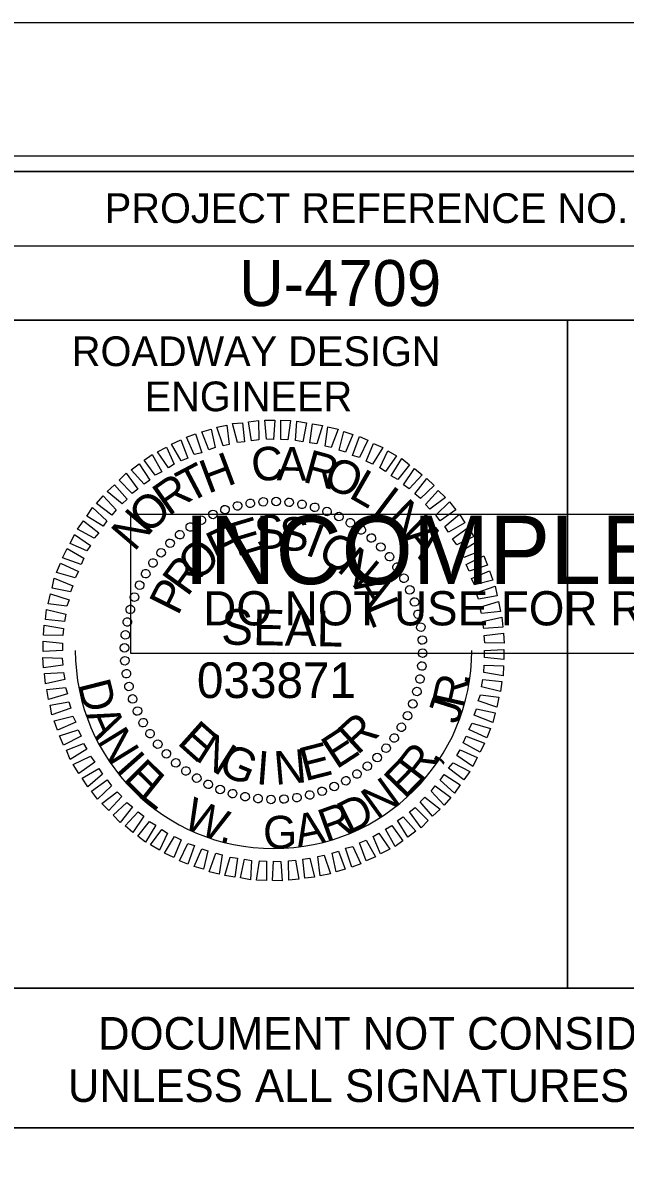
# Model space of a CAD drawing. Extents: x 1779926 to 1781610, y 620464 to 621564.
# Drawn here: x 1781401.3 to 1781502.7, y 621371.7 to 621564.2 of the extents above; entities that cross this region are included whole.
import ezdxf

# ---------------------------------------------------------------- set-up
doc = ezdxf.new("R2010")
doc.units = 0
for name, color, linetype in [('Old_Level_58', 7, 'Continuous'), ('Scratch_Level_0', 7, 'Continuous'), ('Sheet Cutting Line CELL', 7, 'Continuous'), ('Sheet Data Field CELL', 7, 'Continuous'), ('Sheet Plot Border Inside CELL', 7, 'Continuous'), ('Sheet Plot Border Outside CELL', 7, 'Continuous'), ('Sheet Professional Seal CELL', 7, 'Continuous'), ('Sheet Profile CELL', 7, 'Continuous'), ('Sheet Profile Grid Major CELL', 7, 'Continuous'), ('Sheet Profile Grid Minor CELL', 7, 'Continuous'), ('Sheet Sticker Exception Certification CELL', 7, 'Continuous'), ('Sheet Sticker Incomplete CELL', 7, 'Continuous')]:
    doc.layers.add(name, color=color, linetype=linetype)

msp = doc.modelspace()

# ---------------------------------------------------------------- linework, layer by layer
at = {"layer": 'Old_Level_58'}
msp.add_lwpolyline([(1781392.96, 621378.14), (1781592.95, 621378.14), (1781592.95, 621314.19), (1781392.96, 621314.19)], close=True, dxfattribs=at)
at = {"layer": 'Scratch_Level_0'}
msp.add_arc((1781443.52, 621458.52), 33.36, 180, 360, dxfattribs=at)
at = {"layer": 'Sheet Cutting Line CELL'}
msp.add_line((1781609.96, 621564.19), (1779925.96, 621564.19), dxfattribs=at)
at = {"layer": 'Sheet Plot Border Inside CELL'}
msp.add_lwpolyline([(1779938.96, 620486.64), (1781605.46, 620486.64), (1781605.46, 621541.74), (1779938.96, 621541.74)], close=True, dxfattribs=at)
at = {"layer": 'Sheet Plot Border Outside CELL'}
msp.add_lwpolyline([(1779925.96, 620464.19), (1781609.96, 620464.19), (1781609.96, 621564.19), (1779925.96, 621564.19)], close=True, dxfattribs=at)
at = {"layer": 'Sheet Professional Seal CELL'}
for p, q in [((1781437.42, 621482.87), (1781437.42, 621482.87)), ((1781439.62, 621483.27), (1781439.62, 621483.27)), ((1781441.77, 621483.57), (1781441.77, 621483.57)), ((1781443.97, 621483.62), (1781443.97, 621483.62)), ((1781446.17, 621483.47), (1781446.17, 621483.47)), ((1781448.32, 621483.12), (1781448.32, 621483.12)), ((1781450.42, 621482.67), (1781450.42, 621482.67)), ((1781433.32, 621481.47), (1781433.32, 621481.47)), ((1781435.32, 621482.27), (1781435.32, 621482.27)), ((1781452.52, 621481.97), (1781452.52, 621481.97)), ((1781454.52, 621481.07), (1781454.52, 621481.07)), ((1781429.47, 621479.32), (1781429.47, 621479.32)), ((1781431.37, 621480.47), (1781431.37, 621480.47)), ((1781456.47, 621480.07), (1781456.47, 621480.07)), ((1781458.27, 621478.82), (1781458.27, 621478.82)), ((1781427.72, 621478.07), (1781427.72, 621478.07)), ((1781460.02, 621477.47), (1781460.02, 621477.47)), ((1781424.57, 621475.02), (1781424.57, 621475.02)), ((1781426.07, 621476.57), (1781426.07, 621476.57)), ((1781461.57, 621475.97), (1781461.57, 621475.97)), ((1781423.22, 621473.27), (1781423.22, 621473.27)), ((1781463.07, 621474.32), (1781463.07, 621474.32)), ((1781421.97, 621471.47), (1781421.97, 621471.47)), ((1781464.32, 621472.57), (1781464.32, 621472.57)), ((1781420.97, 621469.52), (1781420.97, 621469.52)), ((1781465.47, 621470.67), (1781465.47, 621470.67)), ((1781420.07, 621467.52), (1781420.07, 621467.52)), ((1781466.47, 621468.72), (1781466.47, 621468.72)), ((1781419.37, 621465.42), (1781419.37, 621465.42)), ((1781467.27, 621466.72), (1781467.27, 621466.72)), ((1781418.92, 621463.32), (1781418.92, 621463.32)), ((1781467.87, 621464.62), (1781467.87, 621464.62)), ((1781468.27, 621462.42), (1781468.27, 621462.42)), ((1781418.57, 621461.17), (1781418.57, 621461.17)), ((1781468.57, 621460.27), (1781468.57, 621460.27)), ((1781418.42, 621458.97), (1781418.42, 621458.97)), ((1781443.52, 621458.52), (1781443.52, 621458.52)), ((1781468.62, 621458.07), (1781468.62, 621458.07)), ((1781418.47, 621456.77), (1781418.47, 621456.77)), ((1781468.47, 621455.87), (1781468.47, 621455.87)), ((1781418.77, 621454.62), (1781418.77, 621454.62)), ((1781468.12, 621453.72), (1781468.12, 621453.72)), ((1781419.17, 621452.42), (1781419.17, 621452.42)), ((1781467.67, 621451.62), (1781467.67, 621451.62)), ((1781419.77, 621450.32), (1781419.77, 621450.32)), ((1781420.57, 621448.32), (1781420.57, 621448.32)), ((1781466.97, 621449.52), (1781466.97, 621449.52)), ((1781421.57, 621446.37), (1781421.57, 621446.37)), ((1781466.07, 621447.52), (1781466.07, 621447.52)), ((1781422.72, 621444.47), (1781422.72, 621444.47)), ((1781465.07, 621445.57), (1781465.07, 621445.57)), ((1781423.97, 621442.72), (1781423.97, 621442.72)), ((1781462.47, 621442.02), (1781462.47, 621442.02)), ((1781463.82, 621443.77), (1781463.82, 621443.77)), ((1781425.47, 621441.07), (1781425.47, 621441.07)), ((1781460.97, 621440.47), (1781460.97, 621440.47)), ((1781427.02, 621439.57), (1781427.02, 621439.57)), ((1781428.77, 621438.22), (1781428.77, 621438.22)), ((1781459.32, 621438.97), (1781459.32, 621438.97)), ((1781430.57, 621436.97), (1781430.57, 621436.97)), ((1781455.67, 621436.57), (1781455.67, 621436.57)), ((1781457.57, 621437.72), (1781457.57, 621437.72)), ((1781432.52, 621435.97), (1781432.52, 621435.97)), ((1781434.52, 621435.07), (1781434.52, 621435.07)), ((1781436.62, 621434.37), (1781436.62, 621434.37)), ((1781451.72, 621434.77), (1781451.72, 621434.77)), ((1781453.72, 621435.57), (1781453.72, 621435.57)), ((1781438.72, 621433.92), (1781438.72, 621433.92)), ((1781440.87, 621433.57), (1781440.87, 621433.57)), ((1781443.07, 621433.42), (1781443.07, 621433.42)), ((1781445.27, 621433.47), (1781445.27, 621433.47)), ((1781447.42, 621433.77), (1781447.42, 621433.77)), ((1781449.62, 621434.17), (1781449.62, 621434.17))]:
    msp.add_line(p, q, dxfattribs=at)
for points in [[(1781435.02, 621492.97), (1781433.97, 621496.12), (1781435.67, 621496.47), (1781436.07, 621493.22)], [(1781437.42, 621493.52), (1781436.62, 621496.72), (1781438.27, 621496.87), (1781438.62, 621493.67)], [(1781439.82, 621493.82), (1781439.27, 621497.02), (1781440.97, 621497.22), (1781441.02, 621493.97)], [(1781442.32, 621494.07), (1781442.07, 621497.32), (1781443.72, 621497.27), (1781443.52, 621494.02)], [(1781444.72, 621494.02), (1781444.72, 621497.27), (1781446.37, 621497.22), (1781445.92, 621493.97)], [(1781447.22, 621493.87), (1781447.42, 621497.12), (1781449.07, 621496.82), (1781448.42, 621493.67)], [(1781449.62, 621493.47), (1781450.07, 621496.67), (1781451.72, 621496.42), (1781450.82, 621493.32)], [(1781452.17, 621492.92), (1781452.67, 621496.17), (1781454.37, 621495.77), (1781453.22, 621492.67)], [(1781427.97, 621490.47), (1781426.37, 621493.27), (1781427.92, 621493.97), (1781429.07, 621490.92)], [(1781430.17, 621491.52), (1781428.87, 621494.42), (1781430.37, 621495.02), (1781431.42, 621491.82)], [(1781432.62, 621492.32), (1781431.47, 621495.32), (1781433.02, 621495.77), (1781433.67, 621492.67)], [(1781454.57, 621492.27), (1781455.32, 621495.37), (1781456.87, 621494.87), (1781455.62, 621491.92)], [(1781456.82, 621491.37), (1781457.97, 621494.52), (1781459.37, 621493.92), (1781457.97, 621491.02)], [(1781425.82, 621489.27), (1781423.97, 621491.97), (1781425.52, 621492.77), (1781426.77, 621489.87)], [(1781459.07, 621490.42), (1781460.32, 621493.37), (1781461.87, 621492.67), (1781460.17, 621489.87)], [(1781461.37, 621489.27), (1781462.72, 621492.12), (1781464.22, 621491.27), (1781462.32, 621488.67)], [(1781423.62, 621488.02), (1781421.77, 621490.57), (1781423.07, 621491.52), (1781424.72, 621488.62)], [(1781463.32, 621487.92), (1781465.07, 621490.82), (1781466.37, 621489.77), (1781464.42, 621487.32)], [(1781419.72, 621484.97), (1781417.52, 621487.17), (1781418.72, 621488.37), (1781420.67, 621485.67)], [(1781421.72, 621486.52), (1781419.57, 621488.92), (1781420.92, 621489.97), (1781422.67, 621487.17)], [(1781465.37, 621486.42), (1781467.22, 621489.17), (1781468.52, 621488.07), (1781466.32, 621485.72)], [(1781418.07, 621483.22), (1781415.52, 621485.27), (1781416.77, 621486.42), (1781418.87, 621484.02)], [(1781467.27, 621484.87), (1781469.32, 621487.47), (1781470.52, 621486.27), (1781468.22, 621484.12)], [(1781416.32, 621481.32), (1781413.72, 621483.27), (1781414.82, 621484.57), (1781417.02, 621482.22)], [(1781469.07, 621483.12), (1781471.22, 621485.47), (1781472.42, 621484.27), (1781469.82, 621482.32)], [(1781414.82, 621479.42), (1781412.12, 621481.12), (1781413.07, 621482.57), (1781415.47, 621480.37)], [(1781470.82, 621481.32), (1781473.12, 621483.57), (1781474.17, 621482.22), (1781471.52, 621480.32)], [(1781472.32, 621479.37), (1781474.77, 621481.47), (1781475.72, 621480.02), (1781472.92, 621478.42)], [(1781413.32, 621477.42), (1781410.52, 621478.92), (1781411.52, 621480.32), (1781414.12, 621478.32)], [(1781473.62, 621477.32), (1781476.27, 621479.22), (1781477.22, 621477.72), (1781474.32, 621476.32)], [(1781412.12, 621475.27), (1781409.27, 621476.52), (1781410.02, 621478.07), (1781412.72, 621476.22)], [(1781474.92, 621475.12), (1781477.72, 621476.87), (1781478.37, 621475.32), (1781475.52, 621474.17)], [(1781411.12, 621472.97), (1781408.02, 621474.12), (1781408.77, 621475.67), (1781411.62, 621474.07)], [(1781410.12, 621470.77), (1781407.02, 621471.67), (1781407.67, 621473.22), (1781410.67, 621471.82)], [(1781475.92, 621472.97), (1781478.87, 621474.47), (1781479.52, 621472.87), (1781476.42, 621471.87)], [(1781476.82, 621470.62), (1781479.87, 621471.92), (1781480.42, 621470.37), (1781477.32, 621469.57)], [(1781409.37, 621468.37), (1781406.27, 621469.02), (1781406.62, 621470.67), (1781409.77, 621469.42)], [(1781477.62, 621468.22), (1781480.82, 621469.37), (1781481.12, 621467.72), (1781477.97, 621467.17)], [(1781408.72, 621465.97), (1781405.62, 621466.37), (1781405.97, 621468.07), (1781409.12, 621467.02)], [(1781408.32, 621463.42), (1781405.12, 621463.72), (1781405.32, 621465.42), (1781408.57, 621464.62)], [(1781478.22, 621465.82), (1781481.37, 621466.77), (1781481.67, 621465.07), (1781478.52, 621464.77)], [(1781478.67, 621463.42), (1781481.92, 621464.12), (1781482.07, 621462.42), (1781478.87, 621462.22)], [(1781408.07, 621461.02), (1781404.82, 621461.12), (1781404.92, 621462.77), (1781408.17, 621462.22)], [(1781478.97, 621461.02), (1781482.22, 621461.42), (1781482.32, 621459.72), (1781479.07, 621459.82)], [(1781408.02, 621458.52), (1781404.77, 621458.37), (1781404.77, 621460.07), (1781408.02, 621459.72)], [(1781479.02, 621458.52), (1781482.27, 621458.67), (1781482.27, 621456.97), (1781479.02, 621457.32)], [(1781408.07, 621456.02), (1781404.82, 621455.62), (1781404.72, 621457.32), (1781407.97, 621457.22)], [(1781478.97, 621456.02), (1781482.22, 621455.92), (1781482.12, 621454.27), (1781478.87, 621454.82)], [(1781408.37, 621453.62), (1781405.12, 621452.92), (1781404.97, 621454.62), (1781408.17, 621454.82)], [(1781478.72, 621453.62), (1781481.92, 621453.32), (1781481.72, 621451.62), (1781478.47, 621452.42)], [(1781408.82, 621451.22), (1781405.67, 621450.27), (1781405.37, 621451.97), (1781408.52, 621452.27)], [(1781409.42, 621448.82), (1781406.22, 621447.67), (1781405.92, 621449.32), (1781409.07, 621449.87)], [(1781478.32, 621451.07), (1781481.42, 621450.67), (1781481.07, 621448.97), (1781477.92, 621450.02)], [(1781477.67, 621448.67), (1781480.77, 621448.02), (1781480.42, 621446.37), (1781477.27, 621447.62)], [(1781410.22, 621446.42), (1781407.17, 621445.12), (1781406.62, 621446.67), (1781409.72, 621447.47)], [(1781476.92, 621446.27), (1781480.02, 621445.37), (1781479.37, 621443.82), (1781476.37, 621445.22)], [(1781411.12, 621444.07), (1781408.17, 621442.57), (1781407.52, 621444.17), (1781410.62, 621445.17)], [(1781475.92, 621444.07), (1781479.02, 621442.92), (1781478.27, 621441.37), (1781475.42, 621442.97)], [(1781412.12, 621441.92), (1781409.32, 621440.17), (1781408.67, 621441.72), (1781411.52, 621442.87)], [(1781413.42, 621439.72), (1781410.77, 621437.82), (1781409.82, 621439.32), (1781412.72, 621440.72)], [(1781474.92, 621441.77), (1781477.77, 621440.52), (1781477.02, 621438.97), (1781474.32, 621440.82)], [(1781414.72, 621437.67), (1781412.27, 621435.57), (1781411.32, 621437.02), (1781414.12, 621438.62)], [(1781473.72, 621439.62), (1781476.52, 621438.12), (1781475.52, 621436.72), (1781472.92, 621438.72)], [(1781416.22, 621435.72), (1781413.92, 621433.47), (1781412.87, 621434.82), (1781415.52, 621436.72)], [(1781472.22, 621437.62), (1781474.92, 621435.92), (1781473.97, 621434.47), (1781471.57, 621436.67)], [(1781417.97, 621433.92), (1781415.82, 621431.57), (1781414.62, 621432.77), (1781417.22, 621434.72)], [(1781470.72, 621435.72), (1781473.32, 621433.77), (1781472.22, 621432.47), (1781470.02, 621434.82)], [(1781419.77, 621432.17), (1781417.72, 621429.57), (1781416.52, 621430.77), (1781418.82, 621432.92)], [(1781468.97, 621433.82), (1781471.52, 621431.77), (1781470.27, 621430.62), (1781468.17, 621433.02)], [(1781421.67, 621430.62), (1781419.82, 621427.87), (1781418.52, 621428.97), (1781420.72, 621431.32)], [(1781465.32, 621430.52), (1781467.47, 621428.12), (1781466.12, 621427.07), (1781464.37, 621429.87)], [(1781467.32, 621432.07), (1781469.52, 621429.87), (1781468.32, 621428.67), (1781466.37, 621431.37)], [(1781423.72, 621429.12), (1781421.97, 621426.22), (1781420.67, 621427.27), (1781422.62, 621429.72)], [(1781463.42, 621429.02), (1781465.27, 621426.47), (1781463.97, 621425.52), (1781462.32, 621428.42)], [(1781425.67, 621427.77), (1781424.32, 621424.92), (1781422.82, 621425.77), (1781424.72, 621428.37)], [(1781427.97, 621426.62), (1781426.72, 621423.67), (1781425.17, 621424.37), (1781426.87, 621427.17)], [(1781461.22, 621427.77), (1781463.07, 621425.07), (1781461.52, 621424.27), (1781460.27, 621427.17)], [(1781430.22, 621425.67), (1781429.07, 621422.52), (1781427.67, 621423.12), (1781429.07, 621426.02)], [(1781432.47, 621424.77), (1781431.72, 621421.67), (1781430.17, 621422.17), (1781431.42, 621425.12)], [(1781454.42, 621424.72), (1781455.57, 621421.72), (1781454.02, 621421.27), (1781453.37, 621424.37)], [(1781456.87, 621425.52), (1781458.17, 621422.62), (1781456.67, 621422.02), (1781455.62, 621425.22)], [(1781459.07, 621426.57), (1781460.67, 621423.77), (1781459.12, 621423.07), (1781457.97, 621426.12)], [(1781434.87, 621424.12), (1781434.37, 621420.87), (1781432.67, 621421.27), (1781433.82, 621424.37)], [(1781437.42, 621423.57), (1781436.97, 621420.37), (1781435.32, 621420.62), (1781436.22, 621423.72)], [(1781439.82, 621423.17), (1781439.62, 621419.92), (1781437.97, 621420.22), (1781438.62, 621423.37)], [(1781442.32, 621423.02), (1781442.32, 621419.77), (1781440.67, 621419.82), (1781441.12, 621423.07)], [(1781444.72, 621422.97), (1781444.97, 621419.72), (1781443.32, 621419.77), (1781443.52, 621423.02)], [(1781447.22, 621423.22), (1781447.77, 621420.02), (1781446.07, 621419.82), (1781446.02, 621423.07)], [(1781449.62, 621423.52), (1781450.42, 621420.32), (1781448.77, 621420.17), (1781448.42, 621423.37)], [(1781452.02, 621424.07), (1781453.07, 621420.92), (1781451.37, 621420.57), (1781450.97, 621423.82)]]:
    msp.add_lwpolyline(points, close=True, dxfattribs=at)
for centre, major_axis in [((1781435.35, 621482.23), (-0.234, 0.681)), ((1781437.45, 621482.86), (-0.174, 0.699)), ((1781439.59, 621483.29), (-0.113, 0.711)), ((1781441.77, 621483.54), (-0.05, 0.718)), ((1781443.96, 621483.6), (0.013, 0.72)), ((1781446.14, 621483.46), (0.075, 0.716)), ((1781448.3, 621483.14), (0.137, 0.707)), ((1781450.43, 621482.63), (0.198, 0.692)), ((1781452.51, 621481.93), (0.258, 0.672)), ((1781431.36, 621480.46), (-0.349, 0.63)), ((1781433.32, 621481.43), (-0.293, 0.658)), ((1781454.51, 621481.06), (0.316, 0.647)), ((1781456.44, 621480.02), (0.371, 0.617)), ((1781427.73, 621478.01), (-0.453, 0.56)), ((1781429.49, 621479.31), (-0.403, 0.597)), ((1781458.26, 621478.81), (0.423, 0.582)), ((1781426.1, 621476.56), (-0.5, 0.518)), ((1781459.97, 621477.45), (0.472, 0.543)), ((1781461.56, 621475.94), (0.518, 0.5)), ((1781424.59, 621474.97), (-0.543, 0.472)), ((1781463.01, 621474.3), (0.56, 0.453)), ((1781423.23, 621473.26), (-0.582, 0.423)), ((1781464.31, 621472.54), (0.597, 0.403)), ((1781422.02, 621471.44), (-0.617, 0.371)), ((1781465.45, 621470.68), (0.63, 0.349)), ((1781420.98, 621469.51), (-0.647, 0.316)), ((1781466.43, 621468.72), (0.658, 0.293)), ((1781420.1, 621467.51), (-0.672, 0.258)), ((1781467.23, 621466.69), (0.681, 0.234)), ((1781419.41, 621465.43), (-0.692, 0.198)), ((1781467.85, 621464.59), (0.699, 0.174)), ((1781418.9, 621463.31), (-0.707, 0.137)), ((1781468.29, 621462.44), (0.711, 0.113)), ((1781418.58, 621461.14), (-0.716, 0.075)), ((1781418.44, 621458.96), (-0.72, 0.013)), ((1781468.54, 621460.27), (0.718, 0.05)), ((1781418.5, 621456.77), (-0.718, -0.05)), ((1781468.59, 621458.08), (0.72, -0.013)), ((1781468.46, 621455.9), (0.716, -0.075)), ((1781418.75, 621454.6), (-0.711, -0.113)), ((1781468.14, 621453.73), (0.707, -0.137)), ((1781419.18, 621452.45), (-0.699, -0.174)), ((1781467.63, 621451.61), (0.692, -0.198)), ((1781419.8, 621450.36), (-0.681, -0.234)), ((1781466.93, 621449.53), (0.672, -0.258)), ((1781420.61, 621448.32), (-0.658, -0.293)), ((1781466.06, 621447.53), (0.647, -0.316)), ((1781421.58, 621446.36), (-0.63, -0.349)), ((1781465.02, 621445.6), (0.617, -0.371)), ((1781422.73, 621444.5), (-0.597, -0.403)), ((1781463.81, 621443.78), (0.582, -0.423)), ((1781424.03, 621442.74), (-0.56, -0.453)), ((1781462.45, 621442.07), (0.543, -0.472)), ((1781425.48, 621441.1), (-0.518, -0.5)), ((1781427.06, 621439.59), (-0.472, -0.543)), ((1781460.94, 621440.48), (0.5, -0.518)), ((1781428.78, 621438.23), (-0.423, -0.582)), ((1781457.54, 621437.73), (0.403, -0.597)), ((1781459.3, 621439.03), (0.453, -0.56)), ((1781430.6, 621437.02), (-0.371, -0.617)), ((1781432.52, 621435.98), (-0.316, -0.647)), ((1781453.72, 621435.61), (0.293, -0.658)), ((1781455.68, 621436.58), (0.349, -0.63)), ((1781434.53, 621435.11), (-0.258, -0.672)), ((1781436.61, 621434.41), (-0.198, -0.692)), ((1781438.73, 621433.9), (-0.137, -0.707)), ((1781440.9, 621433.58), (-0.075, -0.716)), ((1781447.44, 621433.75), (0.113, -0.711)), ((1781449.59, 621434.19), (0.174, -0.699)), ((1781451.68, 621434.81), (0.234, -0.681)), ((1781443.08, 621433.44), (-0.013, -0.72)), ((1781445.27, 621433.5), (0.05, -0.718))]:
    msp.add_ellipse(centre, major_axis=major_axis, ratio=0.999708, dxfattribs=at)
at = {"layer": 'Sheet Profile CELL'}
for p, q in [((1781392.91, 621526.64), (1781592.96, 621526.64)), ((1781492.96, 621514.14), (1781492.96, 621401.69))]:
    msp.add_line(p, q, dxfattribs=at)
for points in [[(1781592.96, 621539.19), (1780092.96, 621539.19), (1780092.96, 620489.19), (1781592.96, 620489.19)], [(1781392.91, 621539.19), (1781592.96, 621539.19), (1781592.96, 621514.14), (1781392.91, 621514.14)], [(1781392.91, 621514.14), (1781492.96, 621514.14), (1781492.96, 621401.64), (1781392.91, 621401.64)], [(1781492.96, 621514.14), (1781592.96, 621514.14), (1781592.96, 621401.64), (1781492.96, 621401.64)]]:
    msp.add_lwpolyline(points, close=True, dxfattribs=at)
at = {"layer": 'Sheet Profile Grid Major CELL'}
msp.add_lwpolyline([(1781142.96, 621039.19), (1781192.96, 621039.19), (1781192.96, 621539.19), (1781242.96, 621539.19), (1781242.96, 621039.19), (1781292.96, 621039.19), (1781292.96, 621539.19), (1781342.96, 621539.19), (1781342.96, 621039.19), (1781392.96, 621039.19), (1781392.96, 621539.19), (1781419.26, 621539.19)], dxfattribs=at)
at = {"layer": 'Sheet Sticker Exception Certification CELL'}
for p, q in [((1781392.91, 621401.64), (1781592.95, 621401.64)), ((1781392.91, 621401.64), (1781592.95, 621401.64)), ((1781592.95, 621378.14), (1781392.91, 621378.14)), ((1781592.95, 621378.14), (1781392.91, 621378.14))]:
    msp.add_line(p, q, dxfattribs=at)
at = {"layer": 'Sheet Sticker Incomplete CELL'}
msp.add_lwpolyline([(1781419.48, 621457.99), (1781419.48, 621481.49), (1781566.48, 621481.49), (1781566.48, 621457.99)], close=True, dxfattribs=at)

# ---------------------------------------------------------------- texts
at = {"layer": 'Sheet Data Field CELL'}
msp.add_text('U-4709', height=7.75, dxfattribs=at).set_placement((1781437.72, 621516.5))
at = {"layer": 'Sheet Professional Seal CELL'}
for s, height, rotation, p in [('C', 5.64, 6.2199, (1781440.07, 621486.87)), ('A', 5.64, 359.0203, (1781444.02, 621487.17)), ('R', 5.64, 344.6211, (1781448.22, 621486.97)), ('T', 5.64, 27.8198, (1781429.22, 621483.22)), ('H', 5.64, 20.6195, (1781432.47, 621484.87)), ('O', 5.64, 337.4212, (1781451.57, 621486.22)), ('L', 5.64, 330.2209, (1781455.97, 621484.37)), ('R', 5.64, 35.0205, (1781425.82, 621481.02)), ('O', 5.64, 42.2217, (1781422.37, 621477.92)), ('I', 5.64, 323.0201, (1781460.02, 621481.97)), ('N', 5.64, 315.8189, (1781462.17, 621480.42)), ('N', 5.64, 49.4235, (1781420.07, 621475.02)), ('E', 5.64, 16.6111, (1781437.27, 621474.32)), ('S', 5.64, 7.2556, (1781440.72, 621475.37)), ('S', 5.64, 357.9004, (1781444.32, 621475.42)), ('F', 5.64, 25.967, (1781434.07, 621472.82)), ('I', 5.64, 339.1896, (1781448.62, 621474.72)), ('A', 5.64, 308.6172, (1781465.12, 621477.47)), ('O', 5.64, 44.6812, (1781430.77, 621469.87)), ('O', 5.64, 329.8335, (1781450.62, 621474.02)), ('N', 5.64, 320.4766, (1781453.97, 621472.02)), ('R', 5.64, 54.0397, (1781429.02, 621467.42)), ('P', 5.64, 63.3989, (1781427.42, 621464.22)), ('A', 5.64, 301.7603, (1781456.82, 621469.42)), ('L', 5.64, 292.4008, (1781458.77, 621465.97)), ('SEAL', 5.998, 359, (1781434.67, 621459.52)), ('E', 5.64, 318.2769, (1781427.12, 621442.87)), ('R', 5.64, 42.4814, (1781457.62, 621440.77)), ('N', 5.64, 327.634, (1781430.12, 621440.17)), ('E', 5.64, 33.1241, (1781454.07, 621438.42)), ('G', 5.64, 336.9902, (1781433.92, 621437.92)), ('E', 5.64, 14.4118, (1781448.77, 621436.47)), ('I', 5.64, 355.7012, (1781440.47, 621436.02)), ('N', 5.64, 5.0564, (1781443.82, 621435.87))]:
    msp.add_text(s, height=height, rotation=rotation, dxfattribs=at).set_placement(p)
at = {"layer": 'Sheet Profile CELL'}
for s, height, p in [('PROJECT REFERENCE NO.', 5.0001, (1781415.12, 621530.5)), ('ROADWAY DESIGN', 5.0001, (1781409.57, 621506.4)), ('ENGINEER', 5, (1781421.82, 621498.8))]:
    msp.add_text(s, height=height, dxfattribs=at).set_placement(p)
at = {"layer": 'Sheet Profile Grid Minor CELL'}
msp.add_text('033871', height=5.998, dxfattribs=at).set_placement((1781430.62, 621450.51))
for s, rotation, p in [('D', 284.2682, (1781410.53, 621452.88)), ('R', 77.3541, (1781475.49, 621448.62)), ('.', 84.2805, (1781476.45, 621452.55)), ('J', 72.4855, (1781474.53, 621445.94)), ('A', 293.4128, (1781411.84, 621447.71)), ('N', 301.5986, (1781413.71, 621443.31)), ('R', 52.3788, (1781468.32, 621436.04)), ('I', 311.5304, (1781416.78, 621438.39)), ('E', 315.0508, (1781418.06, 621436.79)), ('E', 45.7958, (1781465.58, 621433.35)), (',', 59.3052, (1781470.85, 621439.2)), ('L', 321.6338, (1781420.72, 621434.01)), ('N', 35.8641, (1781460.91, 621429.92)), ('W', 336.8891, (1781427.97, 621428.88)), ('R', 19.793, (1781452.31, 621426.23)), ('D', 26.7195, (1781456.14, 621427.52)), ('G', 1.6755, (1781441.83, 621425.09)), ('A', 11.6072, (1781447.62, 621425.3)), ('.', 348.4952, (1781434.25, 621426.36))]:
    msp.add_text(s, height=5.5, rotation=rotation, dxfattribs=at).set_placement(p)
at = {"layer": 'Sheet Sticker Exception Certification CELL'}
for s, p in [('DOCUMENT NOT CONSIDERED FINAL', (1781413.98, 621391.3)), ('DOCUMENT NOT CONSIDERED FINAL', (1781413.98, 621391.3)), ('UNLESS ALL SIGNATURES COMPLETED', (1781408.91, 621382.5)), ('UNLESS ALL SIGNATURES COMPLETED', (1781408.91, 621382.5))]:
    msp.add_text(s, height=5.5, dxfattribs=at).set_placement(p)
at = {"layer": 'Sheet Sticker Incomplete CELL'}
for s, height, p in [('INCOMPLETE PLANS', 11.52, (1781428.43, 621469.69)), ('DO NOT USE FOR R/W ACQUISITION', 5.76, (1781431.68, 621462.74))]:
    msp.add_text(s, height=height, dxfattribs=at).set_placement(p)

doc.saveas('drawing.dxf')
